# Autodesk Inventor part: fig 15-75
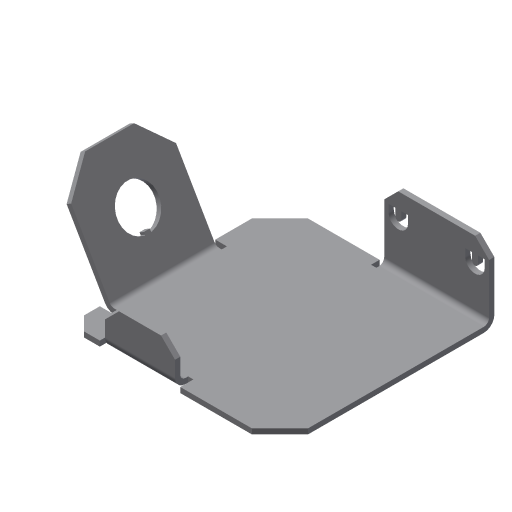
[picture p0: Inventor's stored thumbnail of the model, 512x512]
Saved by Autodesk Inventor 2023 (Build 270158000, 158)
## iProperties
Created: 2002-04
Part Number: fig 15-75
Document SubType Name: Sheet Metal
Density: 1 g/cm^3
Sheet Metal Rule: Default
Material: Generic
Appearance: Default
Control State: 0
Master: False
Checked Out: False
Shininess: 77.0
Angle Display Precision: 2
Document Length Units: 11269
Document Angle Units: 11279
Document Time Units: 11290
Document Mass Units: 11283
Document Length Units Precision: 3
Document Angle Units Precision: 2
Density: 0.0
Volumn: 0.0
Area: 0.0
PropertySet Name: Model Information
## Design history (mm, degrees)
node "Face1"
  sketch "Sketch1"
    geometry: L1 (12.647, 25.882)-(12.647, -14.118); L2 (12.647, -14.118)-(-17.353, -14.118); L3 (-17.353, -14.118)-(-17.353, 15.882); L4 (-17.353, 15.882)-(-2.353, 15.882); L5 (-2.353, 15.882)-(-2.353, 25.882); L6 (-2.353, 25.882)-(12.647, 25.882); 1 further point
    constraints: 12 end point, 4 parallel, 1 perpendicular
    dimensions: "d5" = 30 distance of L2.end L3.end; "d6" = 10 distance of L4.end L5.end; "d7" = 15 distance of L3.end L4.end; "d25" = 15 distance of L5.end L1.start
sketch "Sketch3"
  geometry: L1 (10, -15)-(10, 0)
  constraints: 2 end point
feature "Fold3" sketch "Sketch3" dims "d26" = 0.75 (= BendRadius), "d27" = 90 deg, "d28" = 0.75 (= BendRadius), "d96" = 0.75 (= BendReliefWidth), "d97" = 0.375 (= BendReliefDepth), "d98" = 1.5 (= MinimumRemnant), "d113" = 0.75 (= Thickness), "SeamGap" = 0.01
node "Flange2"
sketch "Sketch6"
  geometry: L1 (-6.914, 3.413)-(-5.843, 3.413); L2 (-5.843, 0.624)-(-6.914, 0.624); L3 (-6.914, 2.432)-(-5.843, 2.432); L4 (-5.843, 1.605)-(-6.914, 1.605); L5 (-6.914, 0.624)-(-6.914, 1.605); L6 (-6.914, 2.432)-(-6.914, 3.413); L7 (-6.914, 12.568)-(-6.914, 11.587); L8 (-6.914, 14.376)-(-6.914, 13.395); L9 (-6.914, 11.587)-(-5.843, 11.587); L10 (-5.843, 14.376)-(-6.914, 14.376); L11 (-6.914, 12.568)-(-5.843, 12.568); L12 (-5.843, 13.395)-(-6.914, 13.395); A1 r 1.394 centre (-5.843, 2.018) between (-5.843, 0.624) and (-5.843, 3.413); A2 r 0.413 centre (-5.843, 2.018) between (-5.843, 1.605) and (-5.843, 2.432); A3 r 1.394 centre (-5.843, 12.982) between (-5.843, 11.587) and (-5.843, 14.376); A4 r 0.413 centre (-5.843, 12.982) between (-5.843, 12.568) and (-5.843, 13.395)
  constraints: 24 end point, 8 point on circle, 4 centre point, 3 equal length, 1 perpendicular
cut "Cut1" sketch "Sketch6" dims "d49" = 0.75 (= Thickness), "d50" = 0
node "Flange3"
feature "Corner Chamfer1" dims "d70" = 4, "d71" = 4, angle "d105" = 45 deg
feature "Corner Chamfer2" dims "d72" = 2, "d73" = 2, angle "d106" = 45 deg
sketch "Sketch10"
  geometry: 1 further point
feature "iFeature15:3" sketch "Sketch10"
body "Solid1"
face "Plate1" dims "d113" = 0.75 (= Thickness)
sketch "Sketch5"
  geometry: L1 (20, 0)-(5, 0); L2 (5, 0)-(5, 15); L3 (5, 15)-(20, 15); L4 (20, 15)-(20, 0)
  constraints: 8 end point
face "Plate6" dims "d35" = 10, "d36" = 5, "d38" = 15, "d39" = 60 deg, "d40" = 0.75 (= BendRadius), "d113" = 0.75 (= Thickness), "MinimumRemnant" = 1.5 (= 2 x Thickness), "BendReliefWidth" = 0.75 (= Thickness)
bend "Bend5" dims "d38" = 15, "d39" = 60 deg, "d40" = 0.75 (= BendRadius), "d99" = 0.75 (= BendReliefWidth), "d100" = 0.375 (= BendReliefDepth), "d101" = 1.5 (= MinimumRemnant), "d113" = 0.75 (= Thickness), "SeamGap" = 0.01, "MinimumRemnant" = 1.5 (= 2 x Thickness), "BendReliefWidth" = 0.75 (= Thickness), "TransitionRadius" = 0.75 (= BendRadius)
sketch "Sketch7"
  geometry: L1 (25, 0)-(15, 0); L2 (15, 0)-(15, 5); L3 (15, 5)-(25, 5); L4 (25, 5)-(25, 0)
  constraints: 8 end point
face "Plate7" dims "d57" = 5, "d58" = 10, "d60" = 5, "d61" = 90 deg, "d62" = 0.75 (= BendRadius), "d113" = 0.75 (= Thickness), "MinimumRemnant" = 1.5 (= 2 x Thickness), "BendReliefWidth" = 0.75 (= Thickness)
bend "Bend7" dims "d59" = 0.75 (= BendRadius), "d60" = 5, "d61" = 90 deg, "d62" = 0.75 (= BendRadius), "d102" = 0.75 (= BendReliefWidth), "d103" = 0.375 (= BendReliefDepth), "d104" = 1.5 (= MinimumRemnant), "d113" = 0.75 (= Thickness), "SeamGap" = 0.01, "MinimumRemnant" = 1.5 (= 2 x Thickness), "BendReliefWidth" = 0.75 (= Thickness)
other parameters: "Thickness" = 0.75, "BendRadius" = 0.75 (= Thickness), "BendReliefDepth" = 0.375 (= 0.5 x Thickness), "CornerReliefSize" = 3 (= 4 x Thickness), "d0" = 0.75 (= BendRadius), "d13" = 0.75 (= BendRadius), "d31" = 0.75 (= BendRadius), "d37" = 0.75 (= BendRadius), "d112" = 0, "JacobiRadiusSize" = 0.75 (= Thickness), "GapSize" = 0.75 (= Thickness)
